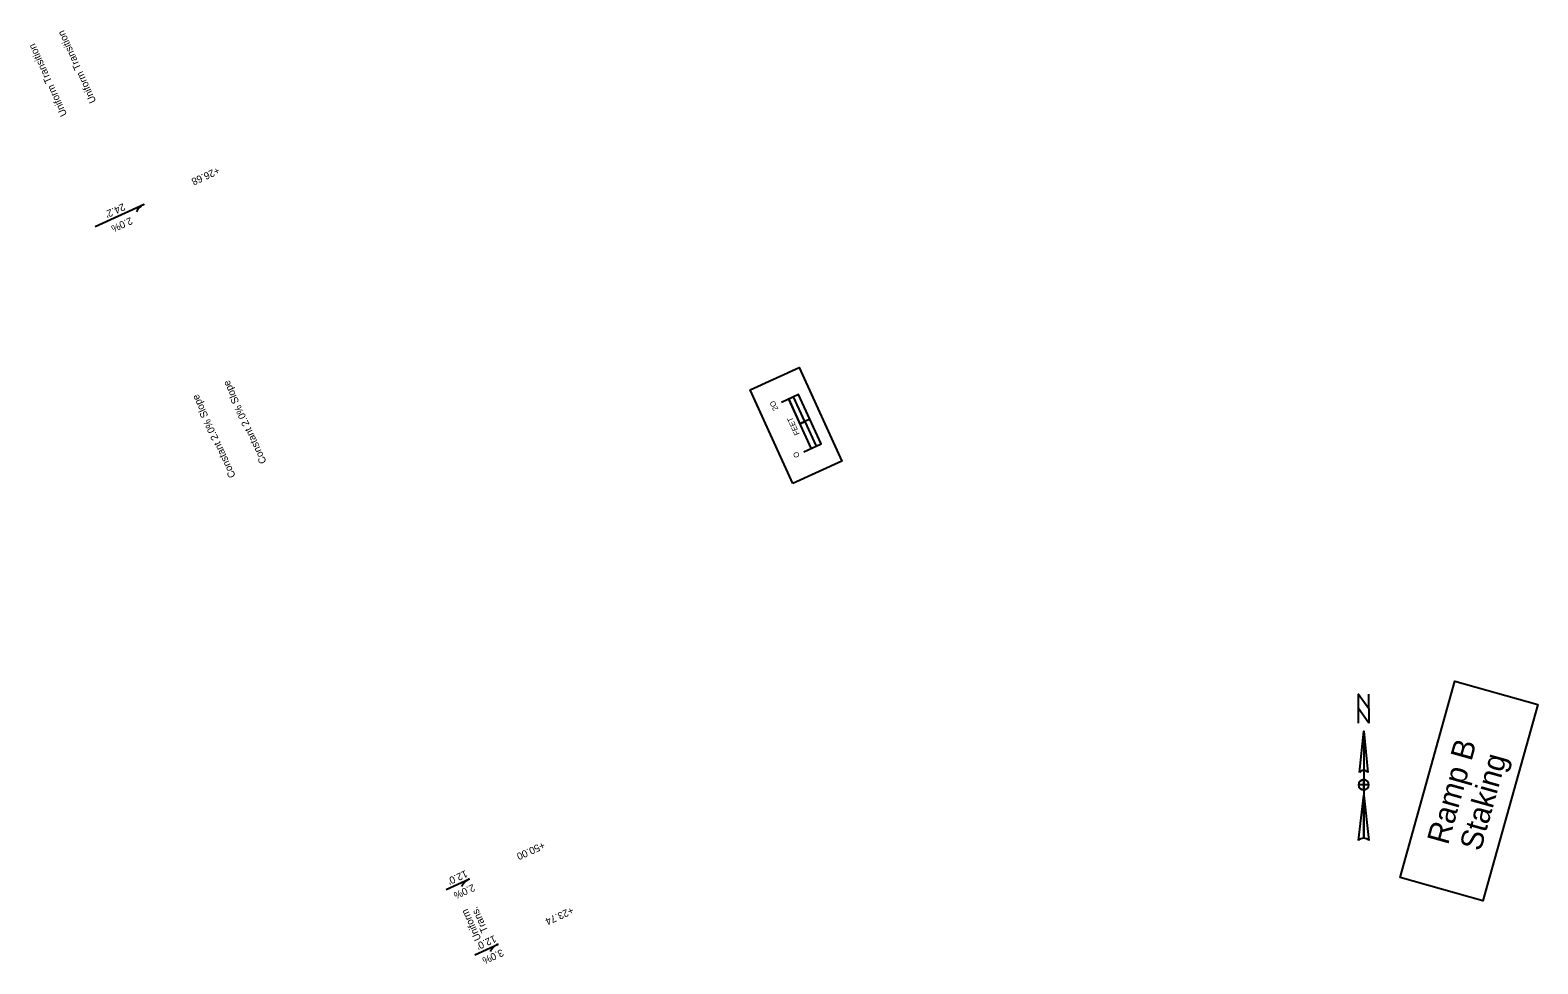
# Model space of a CAD drawing. Extents: x 20506035 to 20507470, y 7969245 to 7972296.
# Drawn here: x 20506913 to 20507470, y 7970776 to 7971121 of the extents above; entities that cross this region are included whole.
import ezdxf

# ---------------------------------------------------------------- set-up
doc = ezdxf.new("R2010")
doc.units = 0
doc.layers.add('_CIVIL_CONSTRUCTION', color=7, linetype='Continuous')
doc.layers.add('EdgeShoulder', color=7, linetype='Continuous')

msp = doc.modelspace()

# ---------------------------------------------------------------- linework, layer by layer
at = {"layer": '_CIVIL_CONSTRUCTION'}
for p, q in [((20506937.23, 7971048.3), (20506955.35, 7971056.55)), ((20507201.24, 7970977.11), (20507197.6, 7970975.45)), ((20507201.24, 7970977.11), (20507197.6, 7970975.45)), ((20507066.85, 7970803.31), (20507075.49, 7970807.25)), ((20507077.44, 7970779.28), (20507086.08, 7970783.22))]:
    msp.add_line(p, q, dxfattribs=at)
for points in [[(20507194.92, 7970953.35), (20507179.17, 7970987.93), (20507197.37, 7970996.22), (20507213.12, 7970961.64)], [(20507194.92, 7970953.35), (20507179.17, 7970987.93), (20507197.37, 7970996.22), (20507213.12, 7970961.64)], [(20507199.41, 7970976.28), (20507195.27, 7970985.38), (20507193.46, 7970984.55), (20507197.6, 7970975.45)], [(20507205.39, 7970968.01), (20507201.24, 7970977.11), (20507199.41, 7970976.28), (20507203.56, 7970967.17)], [(20507470.23, 7970871.74), (20507449.95, 7970799.2), (20507419.32, 7970807.77), (20507439.6, 7970880.3)], [(20507419.32, 7970807.77), (20507439.6, 7970880.3), (20507470.23, 7970871.74), (20507449.95, 7970799.2)]]:
    msp.add_lwpolyline(points, close=True, dxfattribs=at)
for points in [[(20507199.02, 7970965.11), (20507205.39, 7970968.01), (20507197.1, 7970986.21), (20507190.73, 7970983.31)], [(20507201.75, 7970966.35), (20507193.46, 7970984.55)]]:
    msp.add_lwpolyline(points, dxfattribs=at)
for centre in [(20506957.9, 7971050.94), (20507078.05, 7970801.64), (20507088.63, 7970777.61)]:
    msp.add_arc(centre, 6.16, 114.4617, 152.6647, dxfattribs=at)
at = {"layer": 'EdgeShoulder'}
for p, q in [((20507405.88, 7970861.83), (20507407.4, 7970846.61)), ((20507405.88, 7970861.83), (20507405.88, 7970822.28)), ((20507404.36, 7970846.61), (20507404.36, 7970846.61)), ((20507404.42, 7970846.76), (20507404.7, 7970847.07)), ((20507405.88, 7970840.15), (20507405.88, 7970840.15)), ((20507403.98, 7970821.51), (20507405.88, 7970838.25))]:
    msp.add_line(p, q, dxfattribs=at)
msp.add_lwpolyline([(20507407.78, 7970864.87), (20507403.98, 7970870.19), (20507403.98, 7970875.52), (20507407.78, 7970870.19)], close=True, dxfattribs=at)
for points in [[(20507403.98, 7970864.87), (20507403.98, 7970875.52), (20507407.78, 7970870.19), (20507407.78, 7970875.52)], [(20507404.36, 7970846.61), (20507405.88, 7970861.83), (20507405.88, 7970847.38)], [(20507407.78, 7970842.05), (20507405.88, 7970842.05), (20507405.88, 7970843.95)], [(20507405.88, 7970840.15), (20507405.88, 7970842.05), (20507403.98, 7970842.05)], [(20507405.88, 7970822.28), (20507405.88, 7970838.25), (20507407.78, 7970821.51)]]:
    msp.add_lwpolyline(points, dxfattribs=at)
for centre, radius, start, end in [((20507405.88, 7970842.05), 1.9, 90, 180), ((20507405.88, 7970845.47), 1.9, 90.0204, 143.1257), ((20507405.88, 7970845.48), 1.9, 36.8481, 90.0218), ((20507405.88, 7970842.05), 1.9, 0, 90), ((20507405.88, 7970842.05), 1.9, 180, 270), ((20507405.88, 7970842.05), 1.9, 270, 360), ((20507405.88, 7970819.52), 2.76, 89.9894, 133.619), ((20507405.88, 7970819.52), 2.76, 46.4021, 90.0006)]:
    msp.add_arc(centre, radius, start, end, dxfattribs=at)

# ---------------------------------------------------------------- texts
at = {"layer": '_CIVIL_CONSTRUCTION'}
for s, height, rotation, p in [('Uniform Transition', 2.664, 114.3855, (20506937.65, 7971094.55)), ('Uniform Transition', 2.664, 114.3855, (20506926.89, 7971089.65)), ('+26.68', 2.664, 204.4879, (20506982.51, 7971070.39)), ("24.2'", 2.664, 204.5906, (20506947.51, 7971056.95)), ('2.0%', 2.664, 204.5906, (20506950.26, 7971051.83)), ('Constant 2.0% Slope', 2.664, 114.5604, (20507000.61, 7970961.34)), ('Constant 2.0% Slope', 2.664, 114.5604, (20506989.19, 7970956.14)), ('2O', 2, 114.4879, (20507189.68, 7970980.77)), ('FEET', 2, 114.4879, (20507197.55, 7970971.71)), ('O', 2, 114.4879, (20507197.61, 7970963.38)), ('Ramp B', 8.16, 74.3818, (20507437.01, 7970819.54)), ('Staking', 8.16, 74.3818, (20507449.06, 7970817.19)), ('+50.00', 2.664, 204.4879, (20507102.68, 7970821.1)), ("12.0'", 2.664, 204.5906, (20507074.04, 7970810.58)), ('2.0%', 2.664, 204.5906, (20507076.79, 7970805.46)), ('Uniform', 2.664, 114.4338, (20507079.91, 7970785.1)), ('Trans.', 2.664, 114.4338, (20507082.43, 7970788.11)), ('+23.74', 2.664, 204.4879, (20507113.27, 7970797.07)), ("12.0'", 2.664, 204.5906, (20507084.63, 7970786.55)), ('3.0%', 2.664, 204.5906, (20507087.37, 7970781.43))]:
    msp.add_text(s, height=height, rotation=rotation, dxfattribs=at).set_placement(p)

doc.saveas('drawing.dxf')
